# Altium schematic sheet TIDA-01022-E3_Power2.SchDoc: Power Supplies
size 431 x 279 mm; Date: Not shown in title block; ApprovedBy: Not shown in title block; CheckedBy: Not shown in title block; Author: Not shown in title block; CompanyName: Not shown in title block; DrawnBy: Avinash N; Engineer: Not shown in title block; Organization: Not shown in title block; Address1: Not shown in title block; Address2: Not shown in title block; Address3: Not shown in title block; Address4: Not shown in title block; DocumentNumber: 1; Revision: Use project parameter SCH_Rev; SheetNumber: 22; SheetTotal: 26; PageSetup: Record=PageOptions¦CenterHorizontal=True¦CenterVertical=True¦PrintScale=1.00¦XCorrection=1.00¦YCorrection=1.00¦PrintKind=0¦BorderSize=5000000¦LeftOffset=0¦BottomOffset=0¦Orientation=2¦PaperLength=1000¦PaperWidth=1000¦Scale=100¦PaperSource=15¦PrintQuality=600¦MediaType=1¦DitherType=10¦PaperKind=Letter¦PrintScaleMode=1
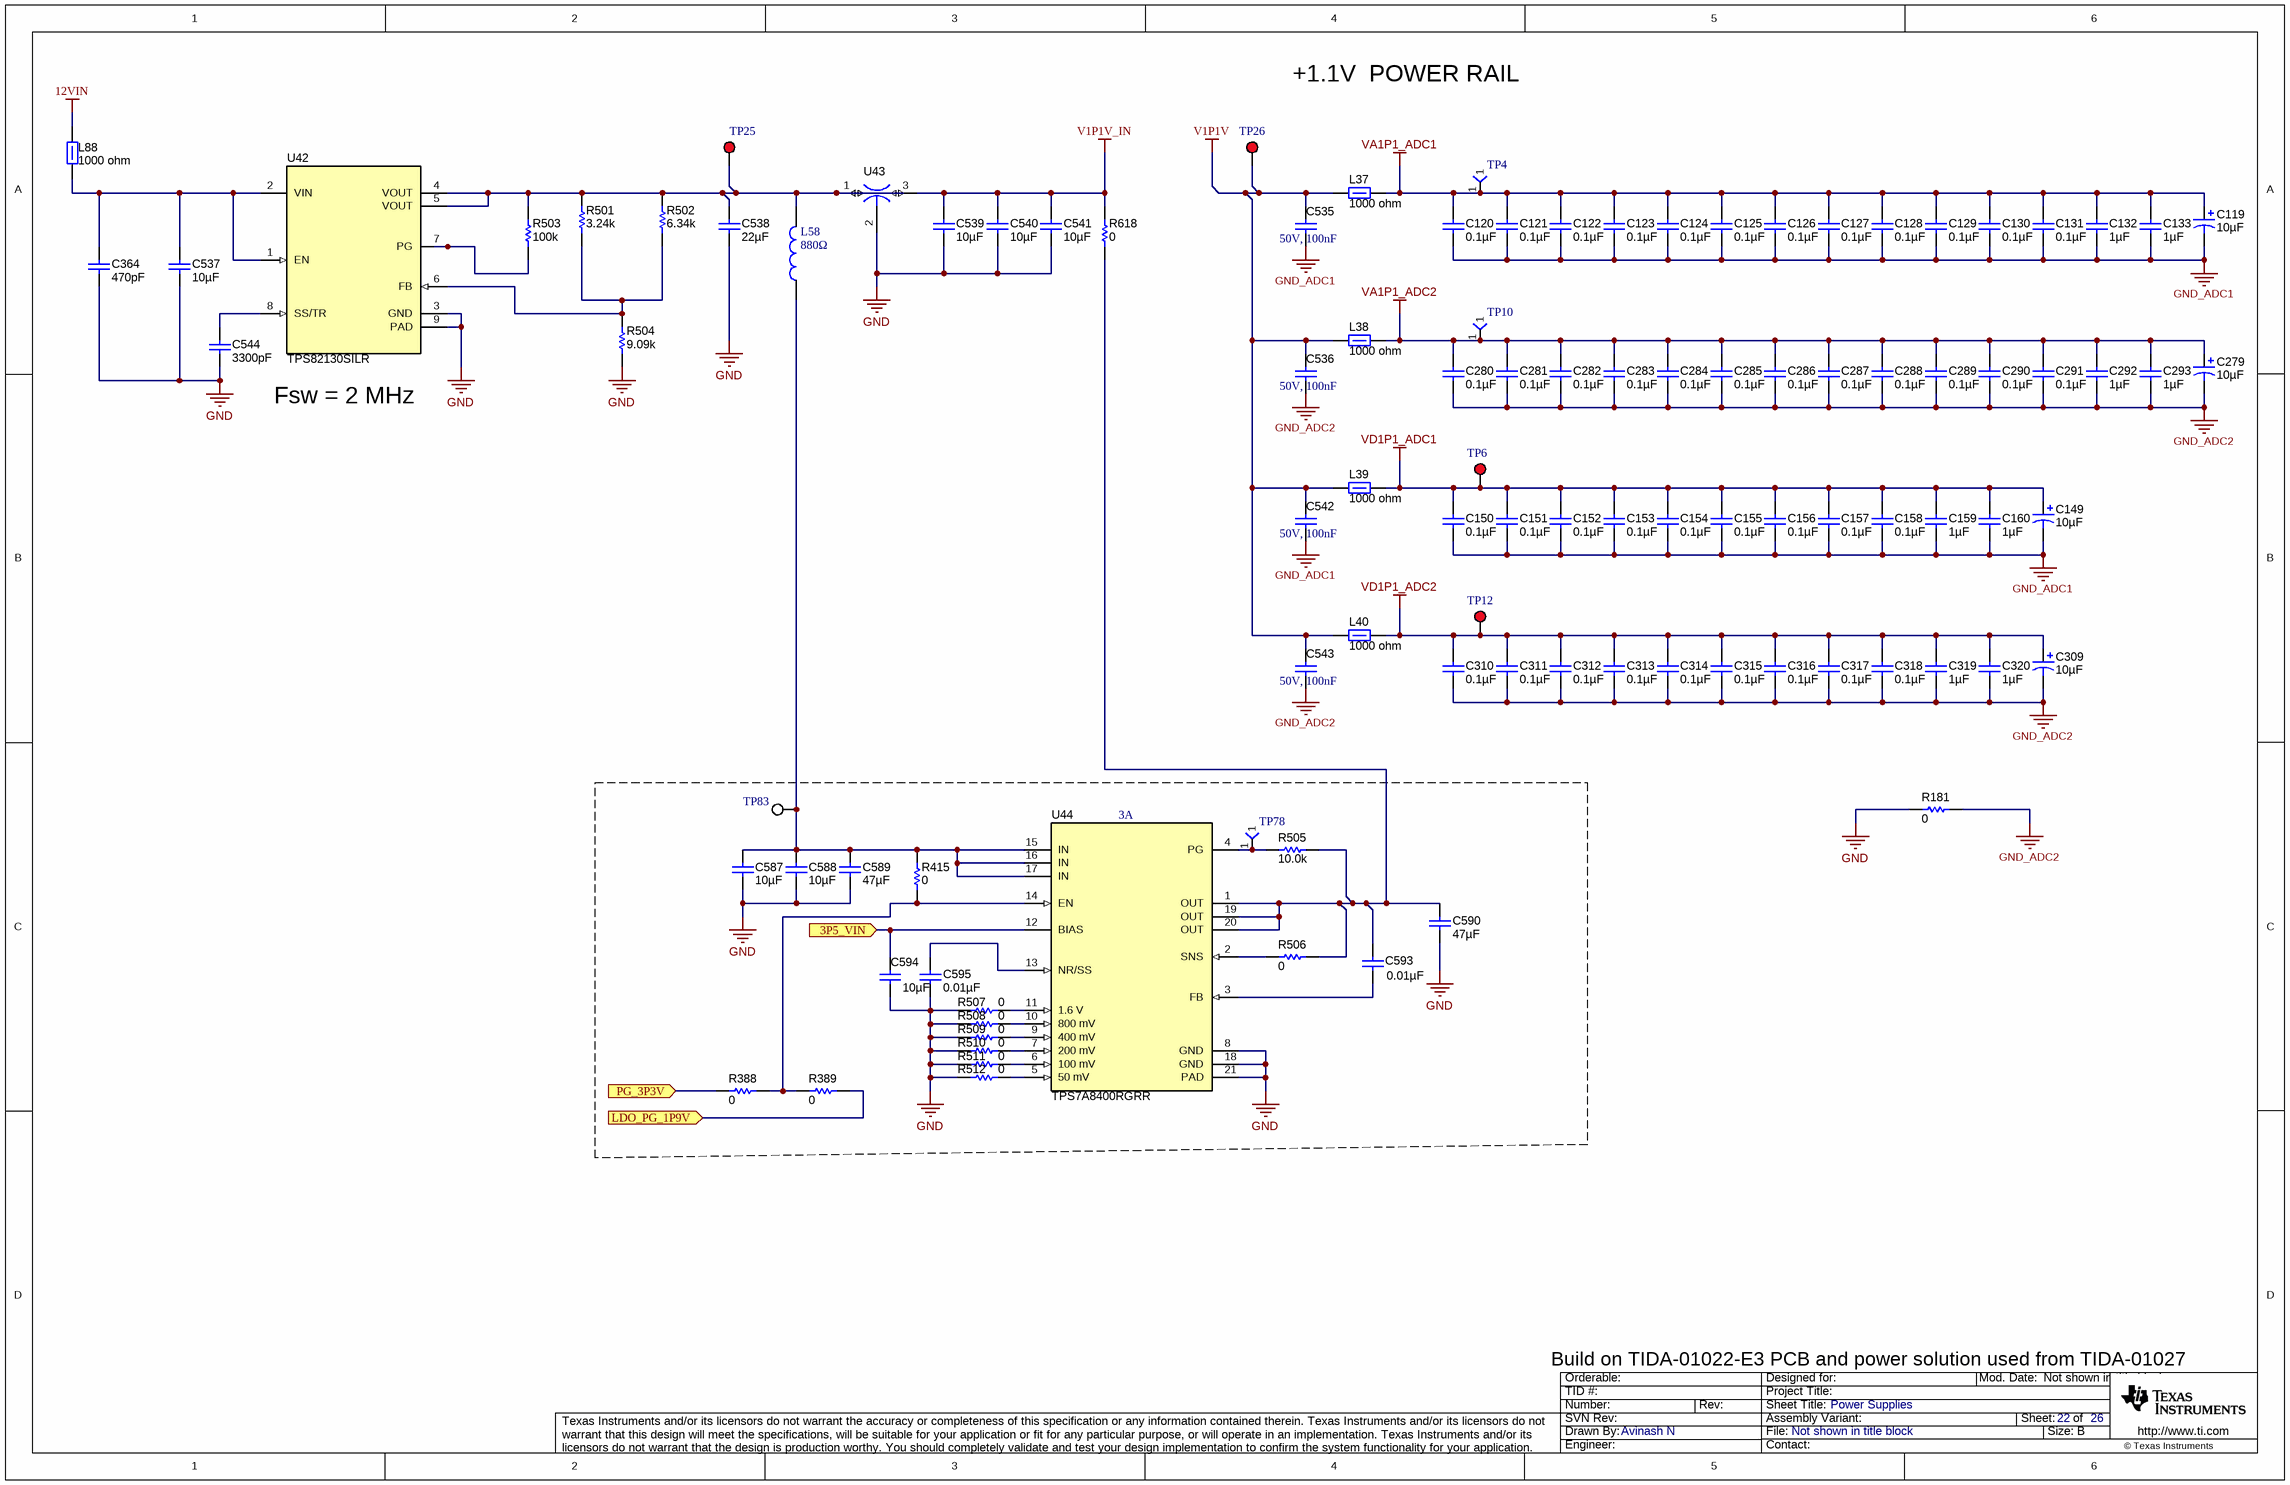
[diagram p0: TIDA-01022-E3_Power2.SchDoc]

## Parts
C119  ValueDisplayed: 10µF  [3528-21]  (hidden comment: 293D106X0010B2TE3)
C120  ValueDisplayed: 0.1µF  [0201]  (hidden comment: GRM033C71A104KE14D)
C121  ValueDisplayed: 0.1µF  [0201]  (hidden comment: GRM033C71A104KE14D)
C122  ValueDisplayed: 0.1µF  [0201]  (hidden comment: GRM033C71A104KE14D)
C123  ValueDisplayed: 0.1µF  [0201]  (hidden comment: GRM033C71A104KE14D)
C124  ValueDisplayed: 0.1µF  [0201]  (hidden comment: GRM033C71A104KE14D)
C125  ValueDisplayed: 0.1µF  [0201]  (hidden comment: GRM033C71A104KE14D)
C126  ValueDisplayed: 0.1µF  [0201]  (hidden comment: GRM033C71A104KE14D)
C127  ValueDisplayed: 0.1µF  [0201]  (hidden comment: GRM033C71A104KE14D)
C128  ValueDisplayed: 0.1µF  [0201]  (hidden comment: GRM033C71A104KE14D)
C129  ValueDisplayed: 0.1µF  [0201]  (hidden comment: GRM033C71A104KE14D)
C130  ValueDisplayed: 0.1µF  [0201]  (hidden comment: GRM033C71A104KE14D)
C131  ValueDisplayed: 0.1µF  [0201]  (hidden comment: GRM033C71A104KE14D)
C132  ValueDisplayed: 1µF  [0603]  (hidden comment: C1608X5R1A105K080AC)
C133  ValueDisplayed: 1µF  [0603]  (hidden comment: C1608X5R1A105K080AC)
C149  ValueDisplayed: 10µF  [3528-21]  (hidden comment: 293D106X0010B2TE3)
C150  ValueDisplayed: 0.1µF  [0201]  (hidden comment: GRM033C71A104KE14D)
C151  ValueDisplayed: 0.1µF  [0201]  (hidden comment: GRM033C71A104KE14D)
C152  ValueDisplayed: 0.1µF  [0201]  (hidden comment: GRM033C71A104KE14D)
C153  ValueDisplayed: 0.1µF  [0201]  (hidden comment: GRM033C71A104KE14D)
C154  ValueDisplayed: 0.1µF  [0201]  (hidden comment: GRM033C71A104KE14D)
C155  ValueDisplayed: 0.1µF  [0201]  (hidden comment: GRM033C71A104KE14D)
C156  ValueDisplayed: 0.1µF  [0201]  (hidden comment: GRM033C71A104KE14D)
C157  ValueDisplayed: 0.1µF  [0201]  (hidden comment: GRM033C71A104KE14D)
C158  ValueDisplayed: 0.1µF  [0201]  (hidden comment: GRM033C71A104KE14D)
C159  ValueDisplayed: 1µF  [0603]  (hidden comment: C1608X5R1A105K080AC)
C160  ValueDisplayed: 1µF  [0603]  (hidden comment: C1608X5R1A105K080AC)
C279  ValueDisplayed: 10µF  [3528-21]  (hidden comment: 293D106X0010B2TE3)
C280  ValueDisplayed: 0.1µF  [0201]  (hidden comment: GRM033C71A104KE14D)
C281  ValueDisplayed: 0.1µF  [0201]  (hidden comment: GRM033C71A104KE14D)
C282  ValueDisplayed: 0.1µF  [0201]  (hidden comment: GRM033C71A104KE14D)
C283  ValueDisplayed: 0.1µF  [0201]  (hidden comment: GRM033C71A104KE14D)
C284  ValueDisplayed: 0.1µF  [0201]  (hidden comment: GRM033C71A104KE14D)
C285  ValueDisplayed: 0.1µF  [0201]  (hidden comment: GRM033C71A104KE14D)
C286  ValueDisplayed: 0.1µF  [0201]  (hidden comment: GRM033C71A104KE14D)
C287  ValueDisplayed: 0.1µF  [0201]  (hidden comment: GRM033C71A104KE14D)
C288  ValueDisplayed: 0.1µF  [0201]  (hidden comment: GRM033C71A104KE14D)
C289  ValueDisplayed: 0.1µF  [0201]  (hidden comment: GRM033C71A104KE14D)
C290  ValueDisplayed: 0.1µF  [0201]  (hidden comment: GRM033C71A104KE14D)
C291  ValueDisplayed: 0.1µF  [0201]  (hidden comment: GRM033C71A104KE14D)
C292  ValueDisplayed: 1µF  [0603]  (hidden comment: C1608X5R1A105K080AC)
C293  ValueDisplayed: 1µF  [0603]  (hidden comment: C1608X5R1A105K080AC)
C309  ValueDisplayed: 10µF  [3528-21]  (hidden comment: 293D106X0010B2TE3)
C310  ValueDisplayed: 0.1µF  [0201]  (hidden comment: GRM033C71A104KE14D)
C311  ValueDisplayed: 0.1µF  [0201]  (hidden comment: GRM033C71A104KE14D)
C312  ValueDisplayed: 0.1µF  [0201]  (hidden comment: GRM033C71A104KE14D)
C313  ValueDisplayed: 0.1µF  [0201]  (hidden comment: GRM033C71A104KE14D)
C314  ValueDisplayed: 0.1µF  [0201]  (hidden comment: GRM033C71A104KE14D)
C315  ValueDisplayed: 0.1µF  [0201]  (hidden comment: GRM033C71A104KE14D)
C316  ValueDisplayed: 0.1µF  [0201]  (hidden comment: GRM033C71A104KE14D)
C317  ValueDisplayed: 0.1µF  [0201]  (hidden comment: GRM033C71A104KE14D)
C318  ValueDisplayed: 0.1µF  [0201]  (hidden comment: GRM033C71A104KE14D)
C319  ValueDisplayed: 1µF  [0603]  (hidden comment: C1608X5R1A105K080AC)
C320  ValueDisplayed: 1µF  [0603]  (hidden comment: C1608X5R1A105K080AC)
C364  ValueDisplayed: 470pF  [0402]  (hidden comment: GRM1555C1H471JA01D)
C535  50V, 100nF  [0603_1.6x0.8x0.8mm_Reflow Soldering]
C536  50V, 100nF  [0603_1.6x0.8x0.8mm_Reflow Soldering]
C537  ValueDisplayed: 10µF  [1206_190]  (hidden comment: C3216X7R1E106M160AE)
C538  ValueDisplayed: 22µF  [0805_HV]  (hidden comment: JMK212BJ226MG-T)
C539  ValueDisplayed: 10µF  [1206_190]  (hidden comment: C3216X7R1E106M160AE)
C540  ValueDisplayed: 10µF  [1206_190]  (hidden comment: C3216X7R1E106M160AE)
C541  ValueDisplayed: 10µF  [1206_190]  (hidden comment: C3216X7R1E106M160AE)
C542  50V, 100nF  [0603_1.6x0.8x0.8mm_Reflow Soldering]
C543  50V, 100nF  [0603_1.6x0.8x0.8mm_Reflow Soldering]
C544  ValueDisplayed: 3300pF  [0603]  (hidden comment: GRM1885C1H332JA01D)
C587  ValueDisplayed: 10µF  [0805_HV]  (hidden comment: GRM21BR61C106KE15L)
C588  ValueDisplayed: 10µF  [0805_HV]  (hidden comment: GRM21BR61C106KE15L)
C589  ValueDisplayed: 47µF  [0805_HV]  (hidden comment: GRM219R60G476ME44D)
C590  ValueDisplayed: 47µF  [0805_HV]  (hidden comment: GRM219R60G476ME44D)
C593  ValueDisplayed: 0.01µF  [0603]  (hidden comment: GRM188R71H103KA01D)
C594  ValueDisplayed: 10µF  [0805_HV]  (hidden comment: GRM21BR61C106KE15L)
C595  ValueDisplayed: 0.01µF  [0603]  (hidden comment: GRM188R71H103KA01D)
L37  ValueDisplayed: 1000 ohm  [1806_HighSpeed]  (hidden comment: BLM41PG102SN1L)
L38  ValueDisplayed: 1000 ohm  [1806_HighSpeed]  (hidden comment: BLM41PG102SN1L)
L39  ValueDisplayed: 1000 ohm  [1806_HighSpeed]  (hidden comment: BLM41PG102SN1L)
L40  ValueDisplayed: 1000 ohm  [1806_HighSpeed]  (hidden comment: BLM41PG102SN1L)
L58  880Ω  [WE-CBF_1812_High Current]
L88  ValueDisplayed: 1000 ohm  [1806_HighSpeed]  (hidden comment: BLM41PG102SN1L)
R181  ValueDisplayed: 0  [1206]  (hidden comment: CRCW12060000Z0EA)
R388  ValueDisplayed: 0  [0603]  (hidden comment: CRCW06030000Z0EA)
R389  ValueDisplayed: 0  [0603]  (hidden comment: CRCW06030000Z0EA)
R415  ValueDisplayed: 0  [0603]  (hidden comment: CRCW06030000Z0EA)
R501  ValueDisplayed: 3.24k  [0402]  (hidden comment: CRCW04023K24FKED)
R502  ValueDisplayed: 6.34k  [0402]  (hidden comment: CRCW04026K34FKED)
R503  ValueDisplayed: 100k  [0402]  (hidden comment: CRCW0402100KFKED)
R504  ValueDisplayed: 9.09k  [0402]  (hidden comment: CRCW04029K09FKED)
R505  ValueDisplayed: 10.0k  [0603]  (hidden comment: CRCW060310K0FKEA)
R506  ValueDisplayed: 0  [0603]  (hidden comment: CRCW06030000Z0EA)
R507  ValueDisplayed: 0  [0402]  (hidden comment: CRCW04020000Z0ED)
R508  ValueDisplayed: 0  [0402]  (hidden comment: CRCW04020000Z0ED)
R509  ValueDisplayed: 0  [0402]  (hidden comment: CRCW04020000Z0ED)
R510  ValueDisplayed: 0  [0402]  (hidden comment: CRCW04020000Z0ED)
R511  ValueDisplayed: 0  [0402]  (hidden comment: CRCW04020000Z0ED)
R512  ValueDisplayed: 0  [0402]  (hidden comment: CRCW04020000Z0ED)
R618  ValueDisplayed: 0  [1206]  (hidden comment: CRCW12060000Z0EA)
TP4  TP-025-SMT  [PROBE_POINT_30PAD]  (value not drawn)
TP6  5000  [Keystone5000]  (value not drawn)
TP10  TP-025-SMT  [PROBE_POINT_30PAD]  (value not drawn)
TP12  5000  [Keystone5000]  (value not drawn)
TP25  5000  [Keystone5000]  (value not drawn)
TP26  5000  [Keystone5000]  (value not drawn)
TP78  TP-025-SMT  [PROBE_POINT_30PAD]  (value not drawn)
TP83  5015  [Testpoint_Keystone_Miniature]  (value not drawn)
U42  TPS82130SILR  [SIL0008D_SMD]
U43  NFM31PC276B0J3L  [Murata_NFM31P]  (value not drawn)
U44  TPS7A8400RGRR  [RGR0020A]

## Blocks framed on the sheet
3A: C587-C590 C593-C595 R388 R389 R415 R505-R512 TP78 TP83 U44

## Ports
3P5_VIN (in), LDO_PG_1P9V (in), PG_3P3V (in)

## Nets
12VIN: L88.2
GND: C364.2 C537.2 C538.2 C539.1 C540.1 C541.1 C544.1 C587.2 C588.2 C589.2 C590.2 C594.2 C595.2 R181.1 R504.1 R507.1 R508.1 R509.1 R510.1 R511.1 R512.1 U42.3(GND) U42.9(PAD) U43.2 U44.8(GND) U44.18(GND) U44.21(PAD)
GND_ADC1: C119.2(-) C120.2 C121.2 C122.2 C123.2 C124.2 C125.2 C126.2 C127.2 C128.2 C129.2 C130.2 C131.2 C132.2 C133.2 C149.2(-) C150.2 C151.2 C152.2 C153.2 C154.2 C155.2 C156.2 C157.2 C158.2 C159.2 C160.2 C535.1 C542.1
GND_ADC2: C279.2(-) C280.2 C281.2 C282.2 C283.2 C284.2 C285.2 C286.2 C287.2 C288.2 C289.2 C290.2 C291.2 C292.2 C293.2 C309.2(-) C310.2 C311.2 C312.2 C313.2 C314.2 C315.2 C316.2 C317.2 C318.2 C319.2 C320.2 C536.1 C543.1 R181.2
V1P1V: C535.2 C536.2 C542.2 C543.2 L37.1 L38.1 L39.1 L40.1 TP26.1
V1P1V_IN: C539.2 C540.2 C541.2 R618.2 U43.3
VA1P1_ADC1: C119.1(+) C120.1 C121.1 C122.1 C123.1 C124.1 C125.1 C126.1 C127.1 C128.1 C129.1 C130.1 C131.1 C132.1 C133.1 L37.2 TP4.1
VA1P1_ADC2: C279.1(+) C280.1 C281.1 C282.1 C283.1 C284.1 C285.1 C286.1 C287.1 C288.1 C289.1 C290.1 C291.1 C292.1 C293.1 L38.2 TP10.1
VD1P1_ADC1: C149.1(+) C150.1 C151.1 C152.1 C153.1 C154.1 C155.1 C156.1 C157.1 C158.1 C159.1 C160.1 L39.2 TP6.1
VD1P1_ADC2: C309.1(+) C310.1 C311.1 C312.1 C313.1 C314.1 C315.1 C316.1 C317.1 C318.1 C319.1 C320.1 L40.2 TP12.1
3P5_VIN: C594.1 U44.12(BIAS) ; port 3P5_VIN
LDO_PG_1P9V: R389.1 ; port LDO_PG_1P9V
PG_3P3V: R388.2 ; port PG_3P3V
NetC364_1: C364.1 C537.1 L88.1 U42.1(EN) U42.2(VIN)
NetC538_1: C538.1 L58.2 R501.2 R502.1 R503.2 TP25.1 U42.4(VOUT) U42.5(VOUT) U43.1
NetC544_2: C544.2 U42.8(SS/TR)
NetC587_1: C587.1 C588.1 C589.1 L58.1 R415.1 TP83.1 U44.15(IN) U44.16(IN) U44.17(IN)
NetC590_1: C590.1 C593.1 R505.1 R506.2 R618.1 U44.1(OUT) U44.19(OUT) U44.20(OUT)
NetC593_2: C593.2 U44.3(FB)
NetC595_1: C595.1 U44.13(NR/SS)
NetR388_1: R388.1 R389.2 R415.2 U44.14(EN)
NetR501_1: R501.1 R502.2 R504.2 U42.6(FB)
NetR503_1: R503.1 U42.7(PG)
NetR505_2: R505.2 TP78.1 U44.4(PG)
NetR506_1: R506.1 U44.2(SNS)
NetR507_2: R507.2 U44.11(1.6_V)
NetR508_2: R508.2 U44.10(800_mV)
NetR509_2: R509.2 U44.9(400_mV)
NetR510_2: R510.2 U44.7(200_mV)
NetR511_2: R511.2 U44.6(100_mV)
NetR512_2: R512.2 U44.5(50_mV)

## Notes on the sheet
- +1.1V  POWER RAIL
- Fsw = 2 MHz
- Build on TIDA-01022-E3 PCB and power solution used from TIDA-01027

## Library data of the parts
C119 C149 C279 C309 = 293D106X0010B2TE3: CAP, TA, 10 µF, 10 V, +/- 20%, 2.5 ohm, SMD; Manufacturer: Vishay-Sprague; Polarized: Y; CompType: Capacitor; Value: 10uF; U/M: EA; Cap_F: 0.00001; Tolerance_%: 20; Value1: 2.5 ohm; VDC_V: 10; Value2: 10V; ESR_ohm: 2.5; IRMS_A: 0.18; TaMin_C: -55; TaMax_C: 125; Cap_Case: B; SizeAreaWB_mm2: 17.1; SizeArea_mm2: 9.8; SizeX_mm: 3.5; SizeY_mm: 2.8; SizeZ_mm: 2.1; AEC Category: Q200
C120-C131 C150-C158 C280-C291 C310-C318 = GRM033C71A104KE14D: CAP, CERM, 0.1 µF, 10 V, +/- 10%, X7S, 0201; Manufacturer: MuRata; Polarized: N; CompType: Capacitor; Value: 0.1uF; U/M: EA; Cap_F: 0.0000001; Tolerance_%: 10; Value1: Unknown; Value2: 10V; TaMin_C: -55; TaMax_C: 125; SizeArea_mm2: 0.18; SizeAreaWB_mm2: 2.08; SizeX_mm: 0.6; SizeY_mm: 0.3; SizeZ_mm: 0.26; AEC Category: Q200
C132 C133 C159 C160 C292 C293 C319 C320 = C1608X5R1A105K080AC: CAP, CERM, 1 µF, 10 V, +/- 10%, X5R, 0603; Manufacturer: TDK; Polarized: N; CompType: Capacitor; Value: 1uF; U/M: EA; Cap_F: 0.000001; Tolerance_%: 10; Value1: Unknown; Value2: 10V; TaMin_C: -55; TaMax_C: 85; SizeArea_mm2: 1.28; SizeAreaWB_mm2: 4.68; SizeX_mm: 1.6; SizeY_mm: 0.8; SizeZ_mm: 1; AEC Category: Q200
C364 = GRM1555C1H471JA01D: CAP, CERM, 470 pF, 50 V, +/- 5%, C0G/NP0, 0402; Manufacturer: MuRata; Polarized: N; CompType: Capacitor; Value: 470pF; U/M: EA; Cap_F: 0.00000000047; Tolerance_%: 5; Value1: Unknown; VDC_V: 50; Value2: 50V; TaMin_C: -55; TaMax_C: 125; SizeArea_mm2: 0.5; SizeAreaWB_mm2: 3; SizeX_mm: 1; SizeZ_mm: 0.6; AEC Category: Q200
C535 C536 C542 C543 = 885012206095: WCAP-CSGP Ceramic Capacitors, 0603, X7R, 50V, 100nF; Rated Voltage: 50V DC
C537 C539-C541 = C3216X7R1E106M160AE: CAP, CERM, 10 µF, 25 V, +/- 20%, X7R, 1206_190; Manufacturer: TDK; Polarized: N; CompType: Capacitor; Value: 10uF; U/M: EA; Cap_F: 0.00001; Tolerance_%: 20; Value1: Unknown; VDC_V: 25; Value2: 25V; TaMin_C: -55; TaMax_C: 125; Cap_Case: 1206; SizeArea_mm2: 5.12; SizeAreaWB_mm2: 10.92; SizeX_mm: 3.2; SizeY_mm: 1.6; SizeZ_mm: 1.9; AEC Category: Q200
C538 = JMK212BJ226MG-T: CAP, CERM, 22 µF, 6.3 V, +/- 20%, X5R, 0805; Manufacturer: Taiyo Yuden; Polarized: N; CompType: Capacitor; Value: 22uF; U/M: EA; Cap_F: 0.000022; Tolerance_%: 20; Value1: Unknown; VDC_V: 6.3; Value2: 6.3V; TaMin_C: -55; TaMax_C: 85; Cap_Case: 0805; SizeArea_mm2: 2.5; SizeAreaWB_mm2: 6.75; SizeX_mm: 2; SizeY_mm: 1.25; SizeZ_mm: 1.45; AEC Category: Q200
C544 = GRM1885C1H332JA01D: CAP, CERM, 3300 pF, 50 V, +/- 5%, C0G/NP0, 0603; Manufacturer: MuRata; Polarized: N; CompType: Capacitor; Value: 3300pF; U/M: EA; Cap_F: 0.0000000033; Tolerance_%: 5; Value1: Unknown; VDC_V: 50; Value2: 50V; TaMin_C: -55; TaMax_C: 125; SizeArea_mm2: 1.28; SizeAreaWB_mm2: 4.68; SizeX_mm: 1.6; SizeY_mm: 0.8; SizeZ_mm: 1; AEC Category: Q200
C587 C588 C594 = GRM21BR61C106KE15L: CAP, CERM, 10 µF, 16 V, +/- 10%, X5R, 0805; Manufacturer: MuRata; Polarized: N; CompType: Capacitor; Value: 10uF; U/M: EA; Cap_F: 0.00001; Tolerance_%: 10; ESR_ohm: 0.008; Value1: 0.008 ohm; VDC_V: 16; Value2: 16V; TaMin_C: -55; TaMax_C: 85; Cap_Case: 0805; SizeArea_mm2: 2.5; SizeAreaWB_mm2: 6.75; SizeX_mm: 2; SizeY_mm: 1.25; SizeZ_mm: 1.45; AEC Category: Q200
C589 C590 = GRM219R60G476ME44D: CAP, CERM, 47 µF, 4 V, +/- 20%, X5R, 0805; Manufacturer: MuRata; Polarized: N; CompType: Capacitor; Value: 47uF; U/M: EA; Cap_F: 0.000047; Tolerance_%: 20; Value1: Unknown; VDC_V: 4; Value2: 4V; TaMin_C: -55; TaMax_C: 85; Cap_Case: 0805; SizeArea_mm2: 2.5; SizeAreaWB_mm2: 6.75; SizeX_mm: 2; SizeY_mm: 1.25; SizeZ_mm: 1.45; AEC Category: Q200
C593 C595 = GRM188R71H103KA01D: CAP, CERM, 0.01 µF, 50 V, +/- 10%, X7R, 0603; Manufacturer: MuRata; Polarized: N; CompType: Capacitor; Value: 0.01uF; U/M: EA; Cap_F: 0.00000001; Tolerance_%: 10; Value1: Unknown; VDC_V: 50; Value2: 50V; TaMin_C: -55; TaMax_C: 125; SizeArea_mm2: 1.28; SizeAreaWB_mm2: 4.68; SizeX_mm: 1.6; SizeY_mm: 0.8; SizeZ_mm: 1; AEC Category: Q200
L37-L40 L88 = BLM41PG102SN1L: Ferrite Bead, 1000 ohm @ 100 MHz, 1.5 A, 1806; Manufacturer: MuRata; Imax_A: 1.5; DCR_ohm: 0.09; Value1: 0.09 ohm; Value2: 1.5A; SizeAreaWB_mm2: 14.3; SizeArea_mm2: 7.2; SizeX_mm: 4.5; SizeY_mm: 1.6; SizeZ_mm: 1.85; ZTyp@100MHz_Ohm: 1000
L58 = WE-CBF, 74279252: WE-CBF SMD EMI Suppression Ferrite Bead, 1812, 880Ω; Type: High Current
R181 = CRCW12060000Z0EA: RES, 0, 5%, 0.25 W, 1206; Manufacturer: Vishay-Dale; CompType: Resistor; Value: 0; Value_Code: 0000; Tolerance_%: 5; Power_W: 0.25; Value2: 0.25W; VDC_V: 200; TempCo: 200 ppm/C; SizeArea_mm2: 5.12; SizeX_mm: 3.2; SizeY_mm: 1.6; SizeZ_mm: 1.35; EIA_Code: E24; U/M: EA; AEC Category: Q200; Green_Lifecycle: Active; Green_REACh: Passed
R388 R389 R415 = CRCW06030000Z0EA: RES, 0, 5%, 0.1 W, 0603; Manufacturer: Vishay-Dale; CompType: Resistor; Value: 0; Value_Code: 0000; Tolerance_%: 5; Power_W: 0.1; Value2: 0.1W; VDC_V: 75; TempCo: 200 ppm/C; SizeArea_mm2: 1.28; SizeX_mm: 1.6; SizeY_mm: 0.8; SizeZ_mm: 1; EIA_Code: E24; U/M: EA; AEC Category: Q200; Green_Lifecycle: Active; Green_REACh: Passed
R501 = CRCW04023K24FKED: RES, 3.24 k, 1%, 0.063 W, 0402; Manufacturer: Vishay-Dale; CompType: Resistor; Value: 3.24k; Res_ohm: 3240; Value_Code: 3k24; Tolerance_%: 1; Power_W: 0.063; Value2: 0.063W; VDC_V: 50; TempCo: 100 ppm/C; SizeArea_mm2: 0.5; SizeZ_mm: 0.6; EIA_Code: E96; U/M: EA; AEC Category: Q200
R502 = CRCW04026K34FKED: RES, 6.34 k, 1%, 0.063 W, 0402; Manufacturer: Vishay-Dale; CompType: Resistor; Value: 6.34k; Res_ohm: 6340; Value_Code: 6k34; Tolerance_%: 1; Power_W: 0.063; Value2: 0.063W; VDC_V: 50; TempCo: 100 ppm/C; SizeArea_mm2: 0.5; SizeZ_mm: 0.6; EIA_Code: E96; U/M: EA; AEC Category: Q200
R503 = CRCW0402100KFKED: RES, 100 k, 1%, 0.063 W, 0402; Manufacturer: Vishay-Dale; CompType: Resistor; Value: 100k; Res_ohm: 100000; Tolerance_%: 1; Power_W: 0.063; Value2: 0.063W; VDC_V: 50; TempCo: 100 ppm/C; SizeArea_mm2: 0.5; SizeZ_mm: 0.6; EIA_Code: E96; U/M: EA; AEC Category: Q200
R504 = CRCW04029K09FKED: RES, 9.09 k, 1%, 0.063 W, 0402; Manufacturer: Vishay-Dale; CompType: Resistor; Value: 9.09k; Res_ohm: 9090; Value_Code: 9k09; Tolerance_%: 1; Power_W: 0.063; Value2: 0.063W; VDC_V: 50; TempCo: 100 ppm/C; SizeArea_mm2: 0.5; SizeZ_mm: 0.6; EIA_Code: E96; U/M: EA; AEC Category: Q200
R505 = CRCW060310K0FKEA: RES, 10.0 k, 1%, 0.1 W, 0603; Manufacturer: Vishay-Dale; CompType: Resistor; Value: 10.0k; Res_ohm: 10000; Value_Code: 10k0; Tolerance_%: 1; Power_W: 0.1; Value2: 0.1W; VDC_V: 75; TempCo: 100 ppm/C; SizeArea_mm2: 1.28; SizeX_mm: 1.6; SizeY_mm: 0.8; EIA_Code: E96; U/M: EA; AEC Category: Q200
R506 = CRCW06030000Z0EA: RES, 0, 5%, 0.1 W, 0603; Manufacturer: Vishay-Dale; CompType: Resistor; Value: 0; Value_Code: 0000; Tolerance_%: 5; Power_W: 0.1; Value2: 0.1W; VDC_V: 75; TempCo: 200 ppm/C; SizeArea_mm2: 1.28; SizeX_mm: 1.6; SizeY_mm: 0.8; SizeZ_mm: 1; EIA_Code: E24; U/M: EA; AEC Category: Q200
R507-R512 = CRCW04020000Z0ED: RES, 0, 5%, 0.063 W, 0402; Manufacturer: Vishay-Dale; CompType: Resistor; Value: 0; Value_Code: 0000; Tolerance_%: 5; Power_W: 0.063; Value2: 0.063W; VDC_V: 50; TempCo: 200 ppm/C; SizeArea_mm2: 0.5; SizeX_mm: 1; SizeZ_mm: 0.6; EIA_Code: E24; U/M: EA; AEC Category: Q200
R618 = CRCW12060000Z0EA: RES, 0, 5%, 0.25 W, 1206; Manufacturer: Vishay-Dale; CompType: Resistor; Value: 0; Value_Code: 0000; Tolerance_%: 5; Power_W: 0.25; Value2: 0.25W; VDC_V: 200; TempCo: 200 ppm/C; SizeArea_mm2: 5.12; SizeX_mm: 3.2; SizeY_mm: 1.6; SizeZ_mm: 1.35; EIA_Code: E24; U/M: EA; AEC Category: Q200
TP4 TP10 TP78 = TP-025-SMT: Test Point, O.025"; Manufacturer: STD; Value: STD
TP6 TP12 = 5000: Test Point, Miniature, Red, TH; Manufacturer: Keystone; CompType: Test Point Loop; ContactFinish: Silver
TP25 TP26 = 5000: Test Point, Miniature, Red, TH; Manufacturer: Keystone; CompType: Test Point Loop; ContactFinish: Silver; Green_Lifecycle: Active; Green_REACh: Passed
TP83 = 5015: Test Point, Miniature, SMT; Manufacturer: Keystone; CompType: Test Point Loop; Green_Lifecycle: Active; Green_REACh: Passed
U42 = TPS82130SILR: 3-A 17V Step-down Converter Module with Integrated Inductor, SIL0008D (uSIP-8); Alternate PartNumber: TPS82130SILT; Manufacturer: Texas Instruments; SymbolCreator: Altium; SizeArea_mm2: 12.25; SizeAreaWB_mm2: 20.25; SizeX_mm: 3.5; SizeZ_mm: 1.53; CompType: IC; U/M: EA
U43 = NFM31PC276B0J3L: FILTER LC HIGH FREQ 27uF 1206; Manufacturer: MuRata; SymbolCreator: Altium
U44 = TPS7A8400RGRR: High-Current (3 A), High-Accuracy (1%), Low-Noise (4.4 μVRMS), LDO Voltage Regulator, RGR0020A (VQFN-20); Alternate PartNumber: TPS7A8400RGRT; Manufacturer: Texas Instruments; SymbolCreator: a0411947; SizeArea_mm2: 12.25; SizeAreaWB_mm2: 20.25; SizeX_mm: 3.5; SizeZ_mm: 1; CompType: IC; U/M: EA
